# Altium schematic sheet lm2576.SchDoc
size A4
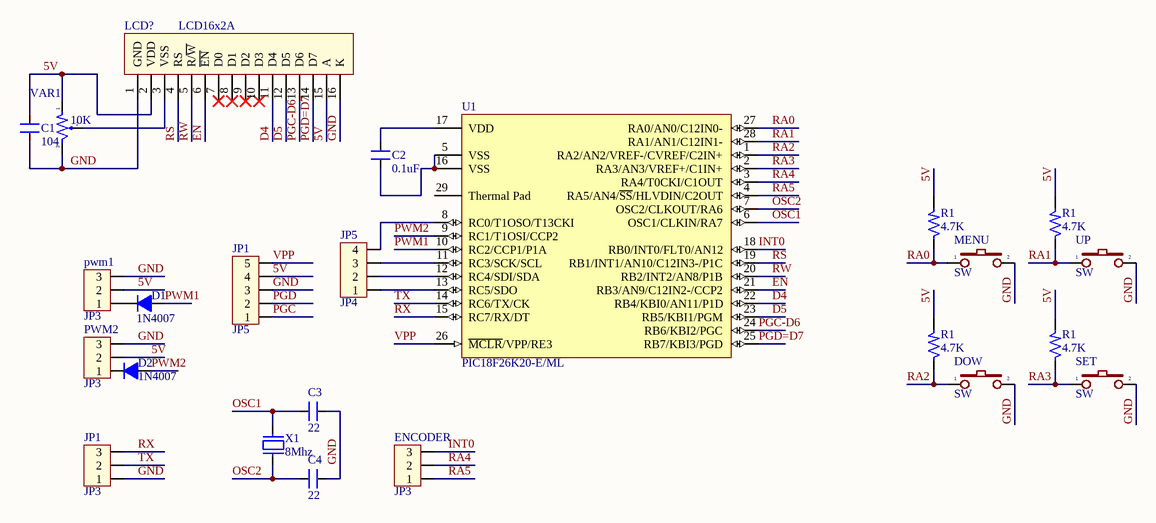
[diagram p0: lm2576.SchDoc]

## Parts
(Parts that share a designator on the sheet are numbered #1, #2 ... from top to bottom, then left to right.)
C1  104  [SM-0805]
C2  0.1uF  [SM-0805]
C3  22  [SM-0805]
C4  22  [SM-0805]
D1  1N4007  [D1A]
D2  1N4007  [D1A]
DOW  SW  [SW2]
ENCODER  JP3  [CON3]
JP1#1  JP5  [CON5]
JP1#2  JP3  [CON3]
JP5  JP4  [CON4]
LCD?  LCD16x2A  [LCD16X2]
MENU  SW  [SW2]
pwm1  JP3  [CON3]
PWM2  JP3  [CON3]
R1#1  4.7K  [SM-1206]
R1#2  4.7K  [SM-1206]
R1#3  4.7K  [SM-1206]
R1#4  4.7K  [SM-1206]
SET  SW  [SW2]
U1  PIC18F26K20-E/ML  [QFN-ML28_N]
UP  SW  [SW2]
VAR1  10K  [VOL-S]
X1  8Mhz  [XT2]

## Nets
5V: C1.2 JP1#1.4 LCD?.2(VDD) LCD?.15(A) pwm1.2 PWM2.2 R1#1.2 R1#2.2 R1#3.2 R1#4.2 VAR1.1
D4: LCD?.11(D4) U1.22(RB4/KBI0/AN11/P1D)
D5: LCD?.12(D5) U1.23(RB5/KBI1/PGM)
EN: LCD?.6(~{EN}) U1.21(RB3/AN9/C12IN2-/CCP2)
GND: C1.1 C3.1 C4.1 DOW.2 JP1#1.3 JP1#2.1 LCD?.1(GND) LCD?.16(K) MENU.2 pwm1.3 PWM2.3 SET.2 UP.2 VAR1.3
INT0: ENCODER.3 U1.18(RB0/INT0/FLT0/AN12)
OSC1: C3.2 U1.6(OSC1/CLKIN/RA7) X1.2
OSC2: C4.2 U1.7(OSC2/CLKOUT/RA6) X1.1
PGC: JP1#1.1
PGC-D6: LCD?.13(D6) U1.24(RB6/KBI2/PGC)
PGD: JP1#1.2
PGD=D7: LCD?.14(D7) U1.25(RB7/KBI3/PGD)
PWM1: D1.1(A) U1.10(RC2/CCP1/P1A)
PWM2: D2.1(A) U1.9(RC1/T1OSI/CCP2)
RA0: MENU.1 R1#1.1 U1.27(RA0/AN0/C12IN0-)
RA1: R1#2.1 U1.28(RA1/AN1/C12IN1-) UP.1
RA2: DOW.1 R1#3.1 U1.1(RA2/AN2/VREF-/CVREF/C2IN+)
RA3: R1#4.1 SET.1 U1.2(RA3/AN3/VREF+/C1IN+)
RA4: ENCODER.2 U1.3(RA4/T0CKI/C1OUT)
RA5: ENCODER.1 U1.4(RA5/AN4/~{SS}/HLVDIN/C2OUT)
RS: LCD?.4(RS) U1.19(RB1/INT1/AN10/C12IN3-/P1C)
RW: LCD?.5(R/~{W}) U1.20(RB2/INT2/AN8/P1B)
RX: JP1#2.3 U1.15(RC7/RX/DT)
TX: JP1#2.2 U1.14(RC6/TX/CK)
VPP: JP1#1.5 U1.26(~{MCLR}/VPP/RE3)
NetC2_1: C2.1 U1.5(VSS) U1.16(VSS)
NetC2_2: C2.2 U1.17(VDD)
NetD1_2: D1.2(K) pwm1.1
NetJP5_1: JP5.1 U1.13(RC5/SDO)
NetJP5_2: JP5.2 U1.12(RC4/SDI/SDA)
NetJP5_3: JP5.3 U1.11(RC3/SCK/SCL)
NetJP5_4: JP5.4 U1.8(RC0/T1OSO/T13CKI)
NetLCD?_3: LCD?.3(VSS) VAR1.2

Not connected (* = marked no-connect by the designer): D2 2(K); LCD? 7(D0)* 8(D1)* 9(D2)* 10(D3)*; PWM2 1; U1 29(Thermal_Pad)

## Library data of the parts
C1-C4 = CM: Cap SMD; Value: 103
D1 D2 = D1A: Diode 1A
DOW MENU SET UP = SW2: Switch button 2 pin; Value: SW chip 2 pin
ENCODER JP1#2 pwm1 PWM2 = Con3: Connector 3
JP1#1 = Con5: Connector 5
JP5 = Con4: Connector 4
LCD? = LCD16x2: LCD dipslay 16 char, 2 line
R1#1-R1#4 = R: Resistor 1/4W; Value: R1/4W - 1K
U1 = PIC18F26K20-E/ML: Flash Microcontroller with 10-Bit A/D and nanoWatt Technology, 64K Flash, 28-Pin QFN, Extended Temperature Range
VAR1 = VOL-S: Var Resistor; Value: Volume 50k
X1 = XT2: Crystal For all Crystal 2pin.; Value: 4Mhz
